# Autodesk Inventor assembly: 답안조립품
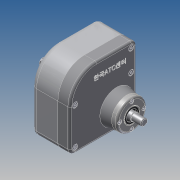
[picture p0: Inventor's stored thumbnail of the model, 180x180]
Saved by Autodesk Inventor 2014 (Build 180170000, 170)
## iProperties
Created: 2015-11
Part Number: 답안조립품
Document SubType Name: Assembly
Designer: kb541
Author: kb541
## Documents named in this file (13)
- C:\Users\kb541\Desktop\201505\20151059138\2급\답안조립품.iam
- C:\Users\kb541\Desktop\201505\20151059138\2급\1-본체.ipt
- C:\Users\kb541\Desktop\201505\20151059138\2급\공용부품_20151104_2\앞커버.ipt
- C:\Users\kb541\Desktop\201505\20151059138\2급\공용부품_20151104_2\로드 축.ipt
- C:\Users\kb541\Desktop\201505\20151059138\2급\공용부품_20151104_2\베어링 6002.ipt
- C:\Users\kb541\Desktop\201505\20151059138\2급\공용부품_20151104_2\로드.ipt
- C:\Users\kb541\Desktop\201505\20151059138\2급\공용부품_20151104_2\오일실 15 x 25.ipt
- C:\Users\kb541\Desktop\201505\20151059138\2급\공용부품_20151104_2\편심 축.ipt
- C:\Users\kb541\Desktop\201505\20151059138\2급\공용부품_20151104_2\베어링 6001.ipt
- C:\Users\kb541\Desktop\201505\20151059138\2급\공용부품_20151104_2\축 커버.ipt
- C:\Users\kb541\Desktop\201505\20151059138\2급\공용부품_20151104_2\오일실 12 x 22.ipt
- C:\Users\kb541\Desktop\201505\20151059138\2급\공용부품_20151104_2\M4 x 0.7.ipt
- C:\Users\kb541\Desktop\201505\20151059138\2급\공용부품_20151104_2\M3 x 0.5.ipt
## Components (10 placed, 3 different names)
1. 1-본체:1 — 플러쉬:1, 플러쉬:2
2. M4 x 0.7:1
3. M4 x 0.7:2
4. M4 x 0.7:3
5. M4 x 0.7:4
6. M4 x 0.7:5
7. M3 x 0.5:1
8. M3 x 0.5:2
9. M3 x 0.5:3
10. M3 x 0.5:4
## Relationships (2: Flush 2)
- 플러쉬:1 [Flush]: 1-본체:1
- 플러쉬:2 [Flush]: 1-본체:1
